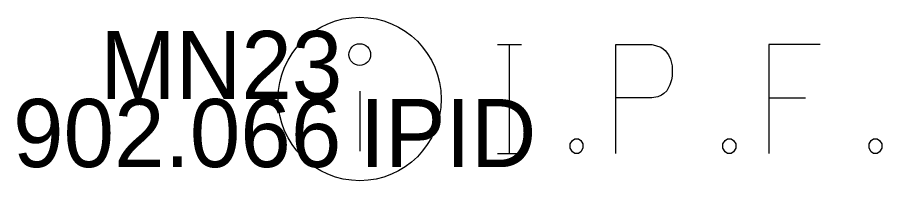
# Model space of a CAD drawing. Extents: x 2228183 to 2230895, y 679226 to 682223.
# Drawn here: x 2228182.77 to 2228195.5, y 680012.02 to 680014.42 of the extents above; entities that cross this region are included whole.
import ezdxf

# ---------------------------------------------------------------- set-up
doc = ezdxf.new("R2010")
doc.units = 0
for name, color, linetype in [('RS_Raster1', 7, 'Continuous'), ('SC_Scratch1', 7, 'Continuous'), ('SV_P_Control_Cells_Set', 7, 'Continuous'), ('SV_X_Text_Comment', 7, 'Continuous')]:
    doc.layers.add(name, color=color, linetype=linetype)

msp = doc.modelspace()

# ---------------------------------------------------------------- linework, layer by layer
at = {"layer": 'RS_Raster1'}
msp.add_line((2228187.811, 680013.339), (2228187.811, 680012.455), dxfattribs=at)
for points in [[(2228189.841, 680014.022), (2228190.194, 680014.022)], [(2228190.018, 680012.422), (2228190.018, 680014.022)], [(2228191.583, 680012.422), (2228191.583, 680014.022), (2228192.112, 680014.022), (2228192.167, 680014.009), (2228192.244, 680013.984), (2228192.278, 680013.959), (2228192.31, 680013.934), (2228192.355, 680013.871), (2228192.388, 680013.808), (2228192.41, 680013.707), (2228192.41, 680013.556), (2228192.399, 680013.505), (2228192.377, 680013.43), (2228192.333, 680013.342), (2228192.288, 680013.304), (2228192.255, 680013.279), (2228192.2, 680013.253), (2228192.112, 680013.241), (2228191.583, 680013.241)], [(2228194.592, 680014.022), (2228193.832, 680014.022), (2228193.832, 680012.422)], [(2228193.832, 680013.241), (2228194.372, 680013.241)], [(2228190.977, 680012.636), (2228191.032, 680012.636), (2228191.065, 680012.611), (2228191.098, 680012.561), (2228191.098, 680012.498), (2228191.065, 680012.447), (2228191.032, 680012.422), (2228190.977, 680012.422), (2228190.944, 680012.447), (2228190.911, 680012.498), (2228190.911, 680012.561), (2228190.944, 680012.611), (2228190.977, 680012.636)], [(2228193.225, 680012.636), (2228193.281, 680012.636), (2228193.314, 680012.611), (2228193.347, 680012.561), (2228193.347, 680012.498), (2228193.314, 680012.447), (2228193.281, 680012.422), (2228193.225, 680012.422), (2228193.192, 680012.447), (2228193.159, 680012.498), (2228193.159, 680012.561), (2228193.192, 680012.611), (2228193.225, 680012.636)], [(2228195.375, 680012.636), (2228195.43, 680012.636), (2228195.463, 680012.611), (2228195.496, 680012.561), (2228195.496, 680012.498), (2228195.463, 680012.447), (2228195.43, 680012.422), (2228195.375, 680012.422), (2228195.342, 680012.447), (2228195.309, 680012.498), (2228195.309, 680012.561), (2228195.342, 680012.611), (2228195.375, 680012.636)], [(2228189.841, 680012.422), (2228190.194, 680012.422)]]:
    msp.add_lwpolyline(points, dxfattribs=at)
for centre, radius in [((2228187.811, 680013.222), 1.2), ((2228187.811, 680013.874), 0.16)]:
    msp.add_circle(centre, radius, dxfattribs=at)

# ---------------------------------------------------------------- texts
at = {"layer": 'SC_Scratch1'}
msp.add_text('902.066', height=1, dxfattribs=at).set_placement((2228182.707, 680012.222))
at = {"layer": 'SV_P_Control_Cells_Set'}
msp.add_text('MN23', height=1, dxfattribs=at).set_placement((2228183.988, 680013.222))
at = {"layer": 'SV_X_Text_Comment'}
msp.add_text('IPID', height=1, dxfattribs=at).set_placement((2228187.811, 680012.222))

doc.saveas('drawing.dxf')
